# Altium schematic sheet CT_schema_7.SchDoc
size 376 x 245 mm
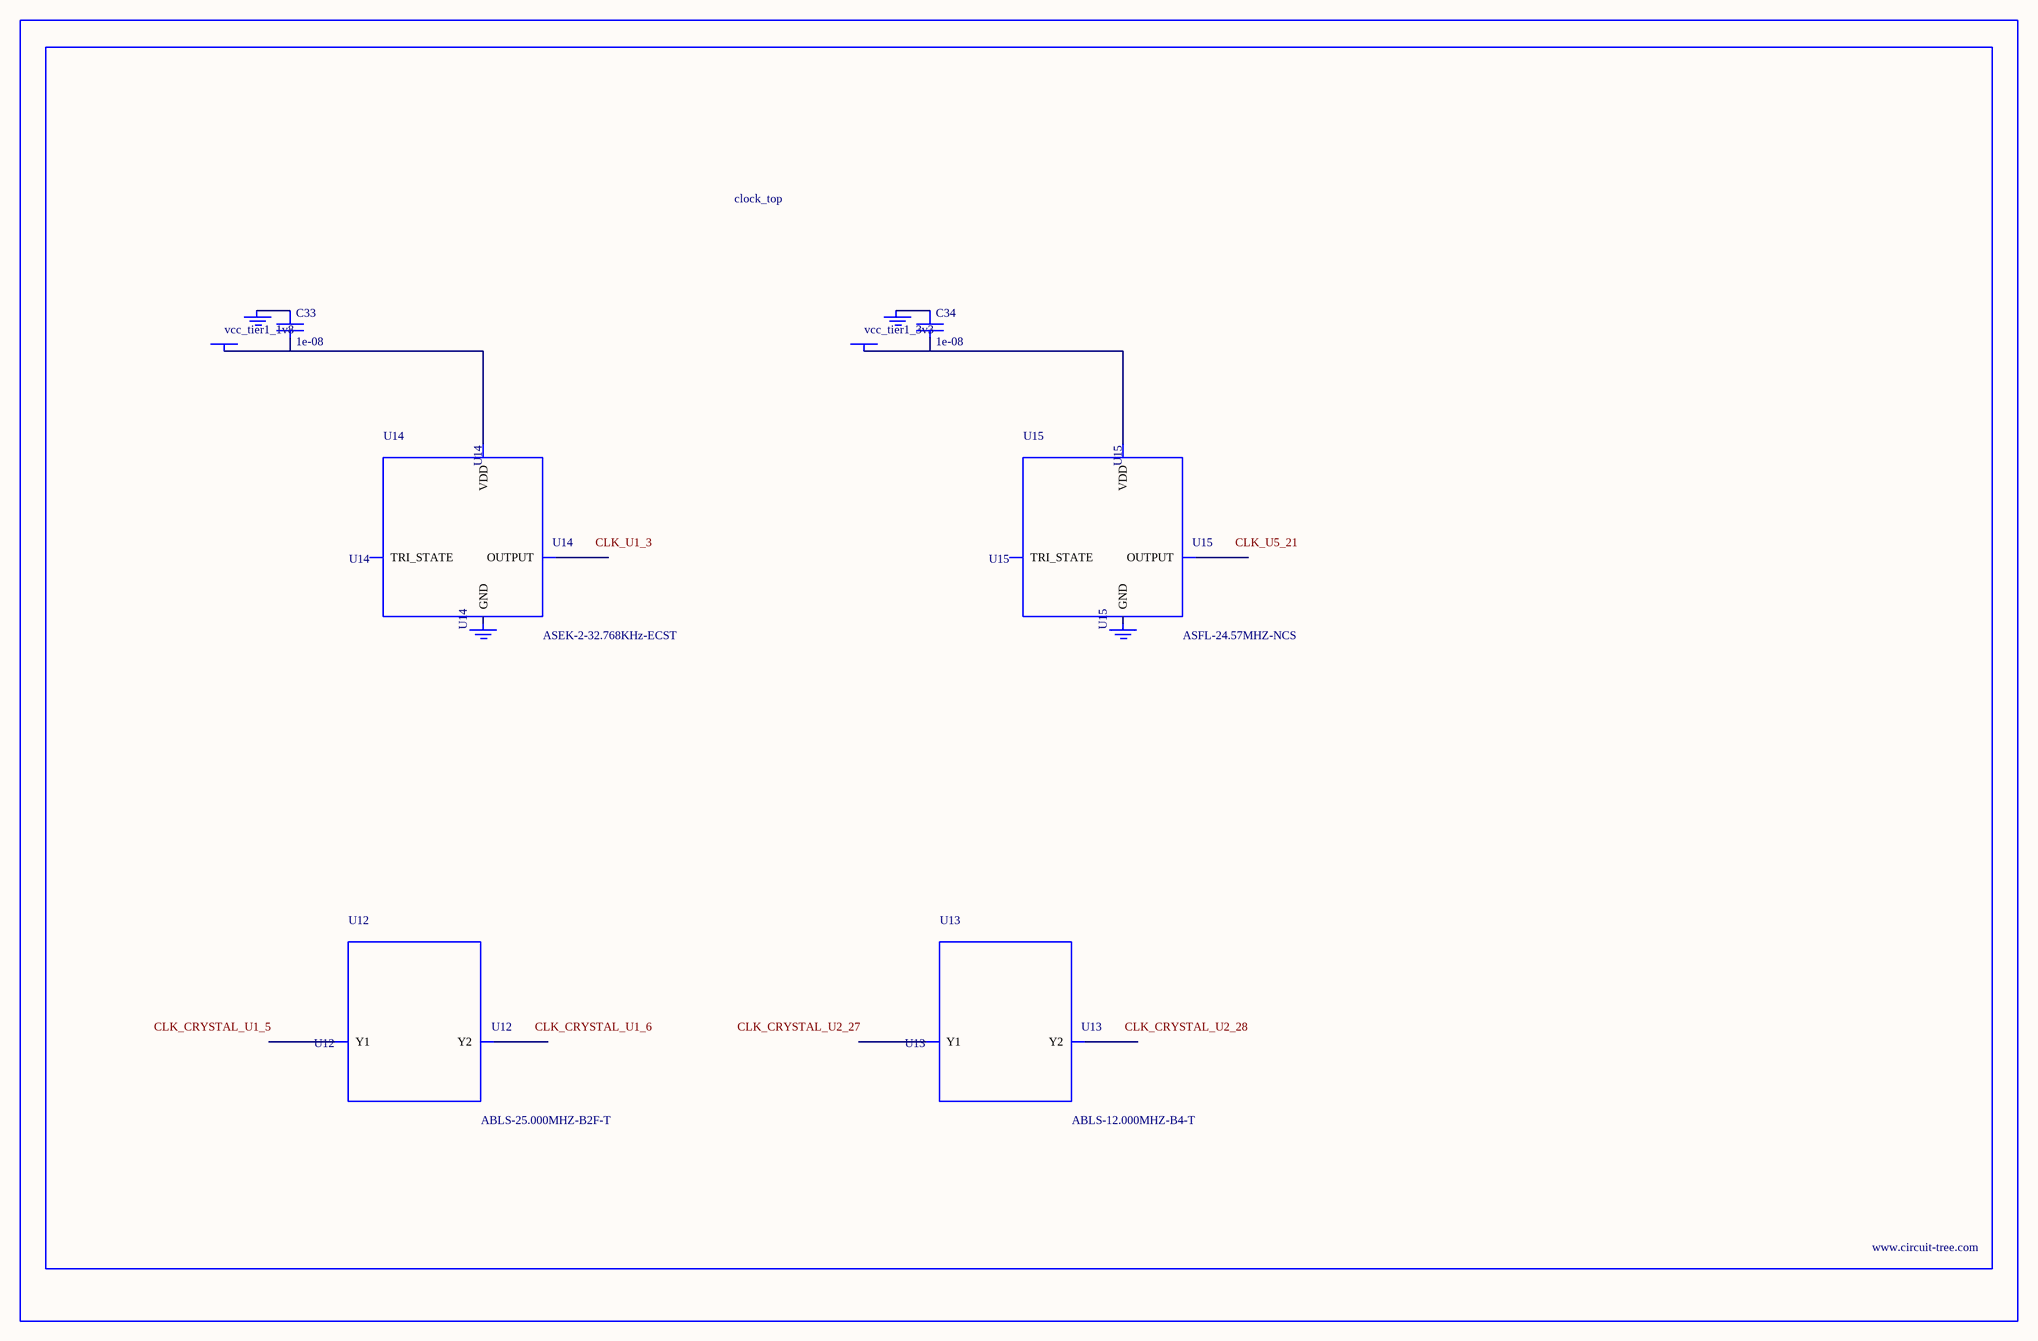
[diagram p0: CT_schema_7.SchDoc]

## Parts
BORDER6  (no value)
C33  1e-08  [C0402]
C34  1e-08  [C0402]
GND_INSTANCE_6_0  (no value)
GND_INSTANCE_6_1  (no value)
GND_INSTANCE_6_2  (no value)
GND_INSTANCE_6_3  (no value)
POWER_INSTANCE_6_0  vcc_tier1_1v8
POWER_INSTANCE_6_1  vcc_tier1_3v3
U12  ABLS-25.000MHZ-B2F-T  [ABLS-25.000MHZ-B2F-T]
U13  ABLS-12.000MHZ-B4-T  [ABLS-12.000MHZ-B4-T]
U14  ASEK-2-32.768KHz-ECST  [ASEK]
U15  ASFL-24.57MHZ-NCS  [ASFL1]

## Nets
NetC33_1: C33.1 GND_INSTANCE_6_0.0(GND)
NetC33_2: C33.2 POWER_INSTANCE_6_0.0(PWR) U14.4(VDD)
NetC34_1: C34.1 GND_INSTANCE_6_2.0(GND)
NetC34_2: C34.2 POWER_INSTANCE_6_1.0(PWR) U15.4(VDD)

Not connected (* = marked no-connect by the designer): GND_INSTANCE_6_1 0(GND); GND_INSTANCE_6_3 0(GND); U12 1(Y1) 2(Y2); U13 1(Y1) 2(Y2); U14 1(TRI_STATE) 2(GND) 3(OUTPUT); U15 1(TRI_STATE) 2(GND) 3(OUTPUT)

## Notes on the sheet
- Labels drawn without touching a wire or pin: CLK_CRYSTAL_U1_5, CLK_CRYSTAL_U1_6, CLK_CRYSTAL_U2_27, CLK_CRYSTAL_U2_28, CLK_U1_3, CLK_U5_21

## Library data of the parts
BORDER6 = BORDER_PAGE6
C33 C34 = C0402C103K3RAC
GND_INSTANCE_6_0-GND_INSTANCE_6_3 = GND
POWER_INSTANCE_6_0 POWER_INSTANCE_6_1 = PWR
